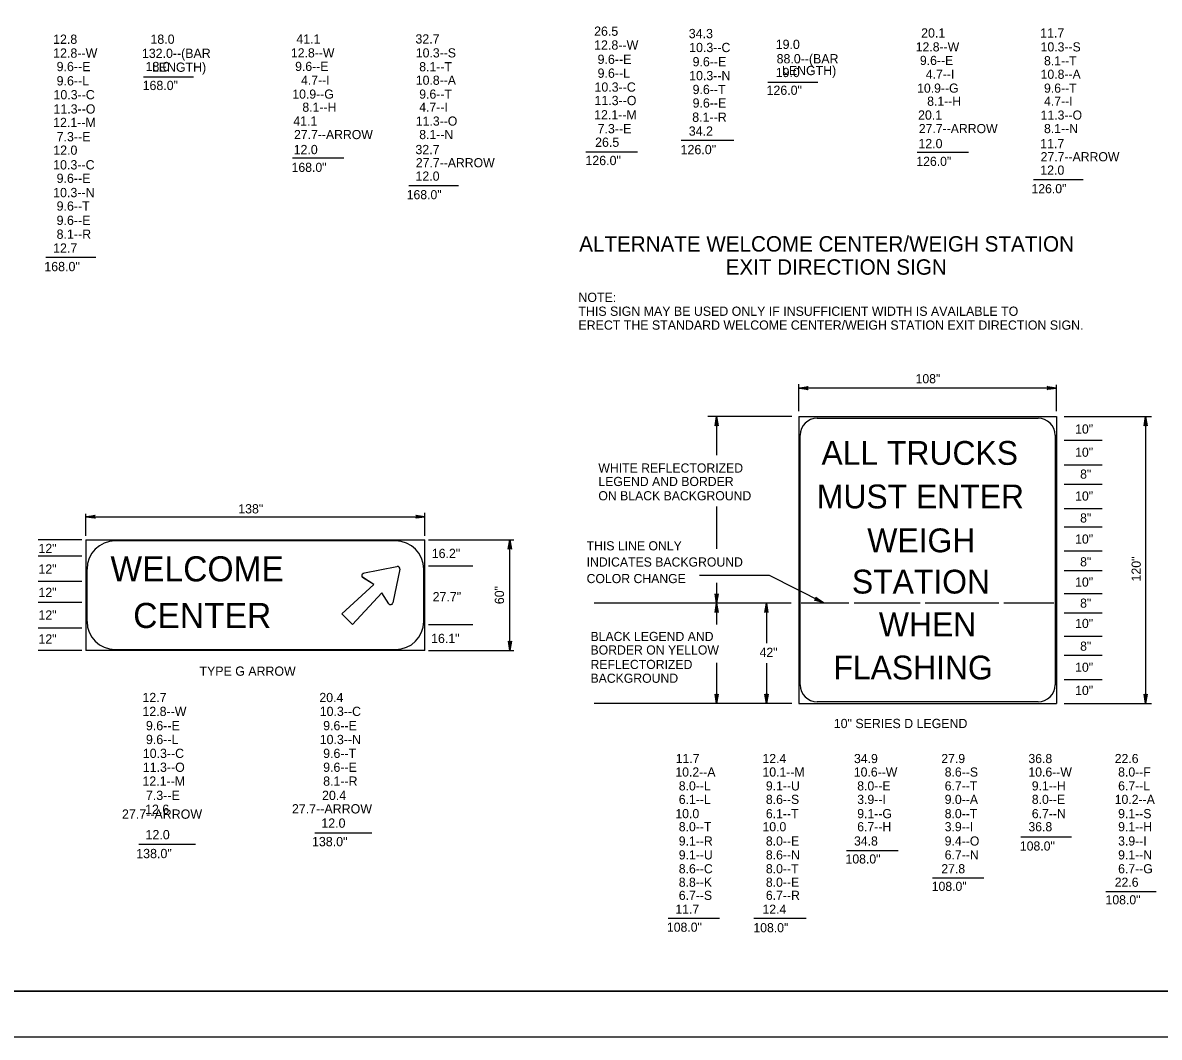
# Model space of a CAD drawing. Extents: x 638689 to 652291, y 298458 to 299646.
# Drawn here: x 651601.9 to 651970.5, y 298457.7 to 298786.8 of the extents above; entities that cross this region are included whole.
import ezdxf

# ---------------------------------------------------------------- set-up
doc = ezdxf.new("R2010")
doc.units = 0
for name, color, linetype in [('1', 7, 'Continuous'), ('2', 7, 'Continuous'), ('3', 7, 'Continuous'), ('PLT-BNDY', 7, 'Continuous')]:
    doc.layers.add(name, color=color, linetype=linetype)

# ---------------------------------------------------------------- blocks, each defined once
blk = doc.blocks.new('RARROW')
at = {"layer": '3'}
blk.add_lwpolyline([(-2.2695, 0.285), (-2.184875, 0.12075), (0, 0), (-2.2695, 0.285), (-2.38575, 0.384625), (0, 0), (-2.183125, -0.108), (-2.262875, -0.2705), (0, 0), (-2.38575, -0.379125), (-2.262875, -0.2705)], dxfattribs=at)

msp = doc.modelspace()

# ---------------------------------------------------------------- linework, layer by layer
at = {"layer": '1'}
for p, q in [((652212.31, 298472.75), (651426.31, 298472.75)), ((651426.31, 298472.75), (652012.31, 298472.75))]:
    msp.add_line(p, q, dxfattribs=at)
at = {"layer": '2'}
for p, q in [((651689.33, 298742.96), (651705.95, 298742.96)), ((651891.97, 298744.89), (651908.59, 298744.89)), ((651727.1, 298734.08), (651743.16, 298734.08)), ((651929.74, 298736.02), (651945.8, 298736.02)), ((651853.54, 298660.81), (651853.54, 298669.56)), ((651937.17, 298668.31), (651853.54, 298668.31)), ((651937.17, 298660.81), (651937.17, 298669.43)), ((651851.29, 298659.06), (651824.04, 298659.06)), ((651826.92, 298659.06), (651826.92, 298646.56)), ((651853.54, 298659.06), (651937.17, 298659.06)), ((651853.54, 298659.06), (651853.54, 298566.06)), ((651859.54, 298658.56), (651931.17, 298658.56)), ((651937.17, 298659.06), (651937.17, 298566.06)), ((651939.67, 298659.06), (651967.92, 298659.06)), ((651966.04, 298659.06), (651966.04, 298566.06)), ((651854.04, 298572.06), (651854.04, 298653.06)), ((651936.67, 298653.06), (651936.67, 298572.06)), ((651939.67, 298651.43), (651951.93, 298651.43)), ((651939.67, 298643.43), (651951.93, 298643.43)), ((651939.67, 298637.18), (651951.93, 298637.18)), ((651622.31, 298620.37), (651622.31, 298627.58)), ((651732.31, 298620.37), (651732.31, 298627.83)), ((651826.92, 298629.87), (651826.92, 298616.18)), ((651939.67, 298629.31), (651951.93, 298629.31)), ((651622.31, 298626.58), (651732.31, 298626.58)), ((651939.67, 298623.31), (651951.93, 298623.31)), ((651621.06, 298619.12), (651606.87, 298619.12)), ((651622.31, 298619.12), (651732.31, 298619.12)), ((651622.31, 298619.12), (651622.31, 298583.25)), ((651722.81, 298618.75), (651631.94, 298618.75)), ((651732.31, 298583.25), (651732.31, 298619.12)), ((651733.44, 298619.12), (651742.06, 298619.12)), ((651733.44, 298619.12), (651761.11, 298619.12)), ((651759.86, 298583.25), (651759.86, 298619.12)), ((651621.06, 298613.75), (651606.87, 298613.75)), ((651939.67, 298615.56), (651951.93, 298615.56)), ((651622.69, 298609.62), (651622.69, 298592.62)), ((651712.19, 298608.25), (651723.19, 298610.5)), ((651712.19, 298608.25), (651723.19, 298610.5)), ((651724.19, 298609.62), (651721.94, 298598.62)), ((651724.19, 298609.62), (651721.94, 298598.62)), ((651731.94, 298592.62), (651731.94, 298609.62)), ((651733.44, 298610.62), (651747.89, 298610.62)), ((651939.67, 298609.18), (651951.93, 298609.18)), ((651621.06, 298605.62), (651606.87, 298605.62)), ((651715.69, 298604.62), (651712.06, 298607)), ((651715.69, 298604.62), (651712.06, 298606.87)), ((651844.04, 298607.56), (651821.38, 298607.56)), ((651826.92, 298605.19), (651826.92, 298598.56)), ((651861.54, 298598.68), (651844.04, 298607.56)), ((651705.31, 298595.12), (651715.69, 298604.62)), ((651705.31, 298595.12), (651715.69, 298604.62)), ((651718.31, 298601.87), (651708.81, 298591.62)), ((651718.31, 298601.87), (651708.81, 298591.62)), ((651720.56, 298598.37), (651718.31, 298601.87)), ((651720.56, 298598.37), (651718.31, 298601.87)), ((651939.67, 298601.68), (651951.93, 298601.68)), ((651621.06, 298598.75), (651606.87, 298598.75)), ((651851.08, 298598.56), (651787.17, 298598.56)), ((651826.92, 298598.56), (651826.92, 298591.68)), ((651843.08, 298598.56), (651843.08, 298585.57)), ((651869.79, 298598.56), (651854.29, 298598.56)), ((651892.92, 298598.56), (651871.54, 298598.56)), ((651918.42, 298598.56), (651894.54, 298598.56)), ((651936.29, 298598.56), (651920.04, 298598.56)), ((651708.81, 298591.62), (651705.31, 298595.12)), ((651708.81, 298591.62), (651705.31, 298595.12)), ((651939.67, 298595.43), (651951.93, 298595.43)), ((651621.06, 298590.5), (651606.87, 298590.5)), ((651733.44, 298591.62), (651747.89, 298591.62)), ((651939.67, 298587.81), (651951.93, 298587.81)), ((651621.06, 298583.25), (651606.87, 298583.25)), ((651732.31, 298583.25), (651622.31, 298583.25)), ((651631.94, 298583.5), (651722.81, 298583.5)), ((651733.44, 298583.25), (651761.11, 298583.25)), ((651826.92, 298579.18), (651826.92, 298566.06)), ((651939.67, 298581.68), (651951.93, 298581.68)), ((651843.08, 298579.06), (651843.08, 298566.06)), ((651939.67, 298573.81), (651951.93, 298573.81)), ((651851.29, 298566.06), (651787.17, 298566.06)), ((651853.54, 298566.06), (651937.17, 298566.06)), ((651931.17, 298566.56), (651859.54, 298566.56)), ((651939.67, 298566.06), (651967.92, 298566.06)), ((651925.56, 298522.81), (651942.04, 298522.81)), ((651869.02, 298518.31), (651885.82, 298518.31)), ((651896.96, 298509.43), (651913.6, 298509.43)), ((651953.18, 298505.06), (651969.5, 298505.06)), ((651811.18, 298496.43), (651827.82, 298496.43)), ((651838.97, 298496.43), (651855.93, 298496.43))]:
    msp.add_line(p, q, dxfattribs=at)
for centre, radius, start, end in [((651859.54, 298653.06), 5.5, 90, 180), ((651931.17, 298653.06), 5.5, 0, 90), ((651631.85, 298609.63), 9.14, 90, 180), ((651722.8, 298609.63), 9.14, 0, 90), ((651723.49, 298609.76), 0.686, 348.2602, 101.7398), ((651723.49, 298609.76), 0.686, 348.2602, 101.7398), ((651712.47, 298607.47), 0.686, 101.7398, 236.6838), ((651712.47, 298607.47), 0.686, 101.7398, 236.6838), ((651721.2, 298598.75), 0.686, 213.3162, 348.2602), ((651721.2, 298598.75), 0.686, 213.3162, 348.2602), ((651631.85, 298592.66), 9.14, 180, 270), ((651722.8, 298592.66), 9.14, 270, 0), ((651859.54, 298572.06), 5.5, 180, 270), ((651931.17, 298572.06), 5.5, 270, 0)]:
    msp.add_arc(centre, radius, start, end, dxfattribs=at)
at = {"layer": '3'}
for p, q in [((651641.01, 298769.32), (651657.26, 298769.32)), ((651843.52, 298767.55), (651859.77, 298767.55)), ((651815.46, 298748.69), (651832.46, 298748.69)), ((651784.5, 298744.97), (651801.27, 298744.97)), ((651609.33, 298710.74), (651625.58, 298710.74)), ((651696.56, 298524.09), (651715.06, 298524.09)), ((651639.56, 298520.34), (651657.94, 298520.34))]:
    msp.add_line(p, q, dxfattribs=at)
at = {"layer": 'PLT-BNDY'}
msp.add_lwpolyline([(651386.31, 299051.75), (652227.31, 299051.75), (652227.31, 298457.75), (651386.31, 298457.75)], close=True, dxfattribs=at)

# ---------------------------------------------------------------- block references
at = {"layer": '2', "xscale": 1.2574347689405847}
for p, yscale, rotation in [((651853.54, 298668.31), 1.3092961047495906, 180), ((651826.92, 298659.06), 1.3092961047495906, 89.99999999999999), ((651966.04, 298659.06), 1.3092961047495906, 89.99999999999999), ((651622.31, 298626.58), 1.3092961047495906, 180), ((651759.86, 298619.12), 1.3092961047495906, 89.99999999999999), ((651826.92, 298598.56), 1.3092961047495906, -90.00000000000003), ((651826.92, 298598.56), 1.3092961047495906, 89.99999999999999), ((651843.08, 298598.56), 1.3092961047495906, 89.99999999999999), ((651861.54, 298598.68), 1.3092961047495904, -26.538667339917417), ((651759.86, 298583.25), 1.3092961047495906, -90.00000000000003), ((651826.92, 298566.06), 1.3092961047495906, -90.00000000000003), ((651843.08, 298566.06), 1.3092961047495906, -90.00000000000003), ((651966.04, 298566.06), 1.3092961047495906, -90.00000000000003)]:
    msp.add_blockref('RARROW', p, dxfattribs=dict(at, yscale=yscale, rotation=rotation))
at = {"layer": '2', "xscale": 1.2574347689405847, "yscale": 1.3092961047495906}
for p in [(651937.17, 298668.31), (651732.31, 298626.58)]:
    msp.add_blockref('RARROW', p, dxfattribs=at)

# ---------------------------------------------------------------- texts
at = {"layer": '2'}
for s, height, p in [('26.5   ', 3, (651787.18, 298782.6)), ('12.8   ', 3, (651611.72, 298779.99)), ('18.0               ', 3, (651643.29, 298780)), ('41.1      ', 3, (651690.61, 298780.08)), ('32.7       ', 3, (651729.23, 298780.08)), ('34.3   ', 3.016, (651817.88, 298781.81)), ('20.1      ', 3, (651893.25, 298782.02)), ('11.7       ', 3, (651931.87, 298782.02)), ('12.8--W', 3.016, (651611.72, 298775.49)), ('132.0--(BAR', 3, (651640.52, 298775.42)), (' 12.8--W    ', 2.9663, (651687.75, 298775.58)), ('10.3--S    ', 2.9663, (651729.36, 298775.58)), ('12.8--W', 3.016, (651787.18, 298778.1)), ('10.3--C', 3, (651818.01, 298777.31)), ('19.0               ', 3, (651846.09, 298778.32)), (' 12.8--W    ', 2.9663, (651890.39, 298777.52)), ('10.3--S    ', 2.9663, (651932, 298777.52)), (' 9.6--E', 3.016, (651787.18, 298773.47)), (' 9.6--E', 3, (651818.01, 298772.69)), ('88.0--(BAR', 3, (651846.38, 298773.66)), ('  9.6--E     ', 2.9663, (651890.64, 298773.13)), (' 8.1--T    ', 2.9663, (651932, 298773.02)), (' 9.6--E', 3.016, (651611.72, 298771.12)), (' 18.0               ', 3, (651640.59, 298771.13)), ('         LENGTH)', 3, (651633.71, 298770.92)), ('  9.6--E     ', 2.9663, (651688.01, 298771.19)), (' 8.1--T    ', 2.9663, (651729.36, 298771.08)), (' 9.6--L', 3.016, (651787.18, 298768.97)), ('10.3--N', 3, (651818.01, 298768.19)), ('19.0               ', 3, (651846.09, 298769.2)), ('         LENGTH)', 3, (651838.07, 298769.84)), (' 4.7--I    ', 2.9663, (651893.66, 298768.64)), ('10.8--A    ', 2.9663, (651932, 298768.64)), (' 9.6--L', 3.016, (651611.72, 298766.49)), ('168.0"              ', 3, (651640.75, 298765)), (' 4.7--I    ', 2.9663, (651691.02, 298766.7)), ('10.8--A    ', 2.9663, (651729.36, 298766.7)), ('10.3--C', 3, (651787.31, 298764.47)), (' 10.9--G    ', 2.9663, (651890.84, 298764.14)), (' 9.6--T    ', 2.9663, (651932, 298764.14)), ('10.3--C', 3, (651611.84, 298761.99)), (' 10.9--G    ', 2.9663, (651688.2, 298762.2)), (' 9.6--T    ', 2.9663, (651729.36, 298762.2)), (' 9.6--T', 3, (651818.01, 298763.69)), ('126.0"', 3, (651843.12, 298763.44)), ('11.3--O', 3, (651611.84, 298757.37)), (' 8.1--H    ', 2.9663, (651691.46, 298757.95)), (' 4.7--I    ', 2.9663, (651729.36, 298757.95)), ('11.3--O', 3, (651787.31, 298760.1)), (' 9.6--E', 3, (651818.01, 298759.31)), (' 8.1--H    ', 2.9663, (651894.1, 298759.89)), (' 4.7--I    ', 2.9663, (651932, 298759.89)), ('12.1--M', 3, (651611.72, 298752.99)), (' 41.1       ', 3, (651688.5, 298753.45)), ('11.3--O    ', 2.9663, (651729.36, 298753.45)), ('12.1--M', 3, (651787.18, 298755.47)), (' 8.1--R', 3.016, (651817.88, 298754.69)), (' 20.1       ', 3, (651891.14, 298755.39)), ('11.3--O    ', 2.9663, (651932, 298755.39)), (' 7.3--E', 3.016, (651787.18, 298750.97)), ('34.2   ', 3.016, (651817.88, 298750.19)), (' 27.7--ARROW', 2.9663, (651891.39, 298751.02)), (' 8.1--N    ', 2.9663, (651932, 298751.02)), (' 7.3--E', 3.016, (651611.72, 298748.37)), (' 27.7--ARROW', 2.9663, (651688.75, 298749.08)), (' 8.1--N    ', 2.9663, (651729.36, 298749.08)), ('26.5', 3, (651787.51, 298746.58)), (' 12.0       ', 3, (651891.25, 298746.14)), ('11.7       ', 3, (651931.87, 298746.14)), ('12.0   ', 3, (651611.77, 298744)), (' 12.0       ', 3, (651688.61, 298744.2)), ('32.7       ', 3, (651729.23, 298744.2)), ('126.0"', 3.016, (651815.23, 298744.19)), ('10.3--C', 3.016, (651611.72, 298739.24)), ('168.0"       ', 2.9663, (651689.06, 298738.45)), ('27.7--ARROW', 2.9663, (651729.36, 298739.95)), ('126.0"   ', 3.016, (651784.35, 298740.65)), ('126.0"       ', 2.9663, (651891.69, 298740.39)), ('27.7--ARROW', 2.9663, (651932, 298741.89)), (' 9.6--E', 3.016, (651611.72, 298734.87)), ('12.0', 3, (651729.24, 298735.58)), ('12.0', 3, (651931.88, 298737.52)), ('126.0"       ', 2.9663, (651929.03, 298731.52)), ('10.3--N', 3.016, (651611.72, 298730.24)), ('168.0"       ', 2.9663, (651726.39, 298729.58)), (' 9.6--T', 3.016, (651611.72, 298725.87)), (' 9.6--E', 3.016, (651611.72, 298721.24)), (' 8.1--R', 3.016, (651611.72, 298716.74)), ('ALTERNATE WELCOME CENTER/WEIGH STATION', 5, (651782.34, 298712.6)), ('12.7   ', 3, (651611.72, 298712.24)), ('168.0"', 3.016, (651608.85, 298706.24)), ('EXIT DIRECTION SIGN', 5, (651829.84, 298705.1)), ('NOTE:', 3, (651782.09, 298696.26)), ('THIS SIGN MAY BE USED ONLY IF INSUFFICIENT WIDTH IS AVAILABLE TO ', 3, (651782.09, 298691.76)), ('ERECT THE STANDARD WELCOME CENTER/WEIGH STATION EXIT DIRECTION SIGN.', 3, (651782.09, 298687.26)), ('108"', 2.966, (651891.44, 298669.89)), ('10"', 2.966, (651943.2, 298653.57)), ('ALL TRUCKS', 7.728, (651860.92, 298643.43)), ('10"', 2.966, (651943.2, 298646.05)), ('WHITE REFLECTORIZED', 2.9663, (651788.56, 298640.92)), ('8"', 2.966, (651944.81, 298638.94)), ('LEGEND AND BORDER', 2.9663, (651788.56, 298636.55)), ('ON BLACK BACKGROUND', 2.9663, (651788.56, 298631.92)), ('MUST ENTER', 7.728, (651859.42, 298629.31)), ('10"', 2.966, (651943.2, 298631.83)), ('138"', 3, (651671.76, 298627.67)), ('8"', 2.966, (651944.81, 298624.72)), ('WEIGH', 7.728, (651875.79, 298615.06)), ('10"', 2.966, (651943.2, 298617.88)), ('12"', 3, (651606.96, 298614.8)), ('16.2"', 3, (651734.52, 298613.19)), ('THIS LINE ONLY', 2.9663, (651784.75, 298615.68)), ('WELCOME', 8.143, (651630.31, 298605.62)), ('INDICATES BACKGROUND', 2.9663, (651784.75, 298610.43)), ('8"', 2.966, (651944.81, 298610.5)), ('12"', 3, (651606.96, 298608.13)), ('STATION', 7.728, (651870.79, 298601.68)), ('COLOR CHANGE', 2.9663, (651784.75, 298605.06)), ('10"', 2.966, (651943.2, 298603.93)), ('12"', 3, (651606.96, 298600.57)), ('27.7"', 3, (651734.81, 298599.15)), ('CENTER', 8.143, (651637.69, 298590.5)), ('8"', 2.966, (651944.81, 298597.09)), ('12"', 3, (651606.96, 298593.23)), ('WHEN', 7.728, (651879.54, 298587.81)), ('10"', 2.966, (651943.2, 298590.51)), ('12"', 3, (651606.96, 298585.45)), ('16.1"', 3, (651734.31, 298585.63)), ('BLACK LEGEND AND', 2.9663, (651786.01, 298586.28)), ('BORDER ON YELLOW', 2.9663, (651786.01, 298581.9)), ('42"', 2.966, (651840.86, 298581.14)), ('8"', 2.966, (651944.81, 298583.13)), ('REFLECTORIZED ', 2.9663, (651786.01, 298577.2)), ('FLASHING', 7.728, (651864.79, 298573.81)), ('10"', 2.966, (651943.2, 298576.29)), ('TYPE G ARROW', 3, (651659.19, 298575.01)), ('BACKGROUND', 2.966, (651786.01, 298572.73)), ('10"', 2.966, (651943.2, 298568.78)), ('12.7   ', 3, (651640.69, 298566.46)), ('20.4   ', 3, (651698.06, 298566.46)), ('12.8--W', 3, (651640.69, 298561.96)), ('10.3--C', 3, (651698.19, 298561.96)), (' 10" SERIES D LEGEND', 3, (651863.8, 298558.03)), (' 9.6--E', 3.016, (651640.69, 298557.34)), (' 9.6--E', 3, (651698.19, 298557.34)), (' 9.6--L', 3.016, (651640.69, 298552.84)), ('10.3--N', 3, (651698.19, 298552.84)), ('10.3--C', 3, (651640.81, 298548.34)), (' 9.6--T', 3, (651698.19, 298548.34)), ('11.7    ', 2.966, (651813.64, 298546.68)), ('12.4   ', 2.966, (651841.79, 298546.68)), ('34.9', 2.966, (651871.48, 298546.68)), ('27.9   ', 2.966, (651899.79, 298546.68)), ('36.8   ', 2.966, (651928.04, 298546.68)), ('22.6   ', 2.966, (651956.04, 298546.68)), ('11.3--O', 3, (651640.81, 298543.84)), (' 9.6--E', 3, (651698.19, 298543.84)), ('12.1--M', 3, (651640.69, 298539.34)), (' 8.1--R', 3, (651698.19, 298539.34)), ('10.2--A', 2.966, (651813.54, 298542.31)), ('10.1--M', 2.966, (651841.79, 298542.31)), ('10.6--W', 2.966, (651871.42, 298542.31)), (' 8.6--S', 2.966, (651899.79, 298542.31)), ('10.6--W', 2.966, (651928.04, 298542.31)), (' 8.0--F', 2.966, (651956.04, 298542.31)), (' 8.0--L', 2.966, (651813.54, 298537.81)), (' 9.1--U', 2.966, (651841.79, 298537.81)), (' 8.0--E', 2.966, (651871.42, 298537.81)), (' 6.7--T', 2.966, (651899.79, 298537.81)), (' 9.1--H', 2.966, (651928.04, 298537.81)), (' 6.7--L', 2.966, (651956.04, 298537.81)), (' 7.3--E', 3.016, (651640.69, 298534.71)), ('20.4  ', 3, (651698.94, 298534.71)), (' 6.1--L', 2.966, (651813.54, 298533.43)), (' 8.6--S', 2.966, (651841.79, 298533.43)), (' 3.9--I', 2.966, (651871.42, 298533.43)), (' 9.0--A', 2.966, (651899.79, 298533.43)), (' 8.0--E', 2.966, (651928.04, 298533.43)), ('10.2--A', 2.966, (651956.04, 298533.43)), ('    27.7--ARROW', 3.0158, (651629.56, 298528.62)), ('12.6  ', 3, (651641.56, 298530.21)), ('     27.7--ARROW', 3.0158, (651683.56, 298530.34)), ('10.0   ', 2.966, (651813.54, 298528.81)), (' 6.1--T', 2.966, (651841.79, 298528.81)), (' 9.1--G', 2.966, (651871.42, 298528.81)), (' 8.0--T', 2.966, (651899.79, 298528.81)), (' 6.7--N', 2.966, (651928.04, 298528.81)), (' 9.1--S', 2.966, (651956.04, 298528.81)), ('12.0   ', 3.016, (651698.69, 298525.71)), (' 8.0--T', 2.966, (651813.54, 298524.56)), ('10.0   ', 2.966, (651841.79, 298524.56)), (' 6.7--H', 2.966, (651871.42, 298524.56)), (' 3.9--I', 2.966, (651899.79, 298524.56)), ('36.8   ', 2.966, (651928.04, 298524.56)), (' 9.1--H', 2.966, (651956.04, 298524.56)), ('12.0   ', 3.016, (651641.69, 298521.96)), ('138.0"   ', 3.016, (651695.67, 298519.71)), (' 9.1--R', 2.966, (651813.54, 298519.93)), (' 8.0--E', 2.966, (651841.79, 298519.93)), ('34.8   ', 2.966, (651871.48, 298519.93)), (' 9.4--O', 2.966, (651899.79, 298519.93)), ('108.0"', 2.966, (651925.27, 298518.31)), (' 3.9--I', 2.966, (651956.04, 298519.93)), ('138.0"   ', 3.016, (651638.67, 298515.84)), (' 9.1--U', 2.966, (651813.54, 298515.43)), (' 8.6--N', 2.966, (651841.79, 298515.43)), ('108.0"', 2.966, (651868.73, 298514.11)), (' 6.7--N', 2.966, (651899.79, 298515.43)), (' 9.1--N', 2.966, (651956.04, 298515.43)), (' 8.6--C', 2.966, (651813.54, 298510.93)), (' 8.0--T', 2.966, (651841.79, 298510.93)), ('27.8   ', 2.966, (651899.79, 298510.93)), (' 6.7--G', 2.966, (651956.04, 298510.93)), (' 8.8--K', 2.966, (651813.54, 298506.56)), (' 8.0--E', 2.966, (651841.79, 298506.56)), ('22.6   ', 2.966, (651956.04, 298506.56)), ('108.0"', 2.966, (651896.68, 298505.22)), (' 6.7--S', 2.966, (651813.54, 298502.31)), (' 6.7--R', 2.966, (651841.79, 298502.31)), ('108.0"', 2.966, (651953.06, 298500.86)), ('11.7   ', 2.966, (651813.54, 298497.81)), ('12.4   ', 2.966, (651841.79, 298497.81)), ('108.0" ', 2.966, (651810.8, 298491.97)), ('108.0"', 2.966, (651838.84, 298491.81))]:
    msp.add_text(s, height=height, dxfattribs=at).set_placement(p)
for s, p in [('120"', (651964.49, 298605.59)), ('60"', (651757.96, 298598.23))]:
    msp.add_text(s, height=3, rotation=90, dxfattribs=at).set_placement(p)

doc.saveas('drawing.dxf')
